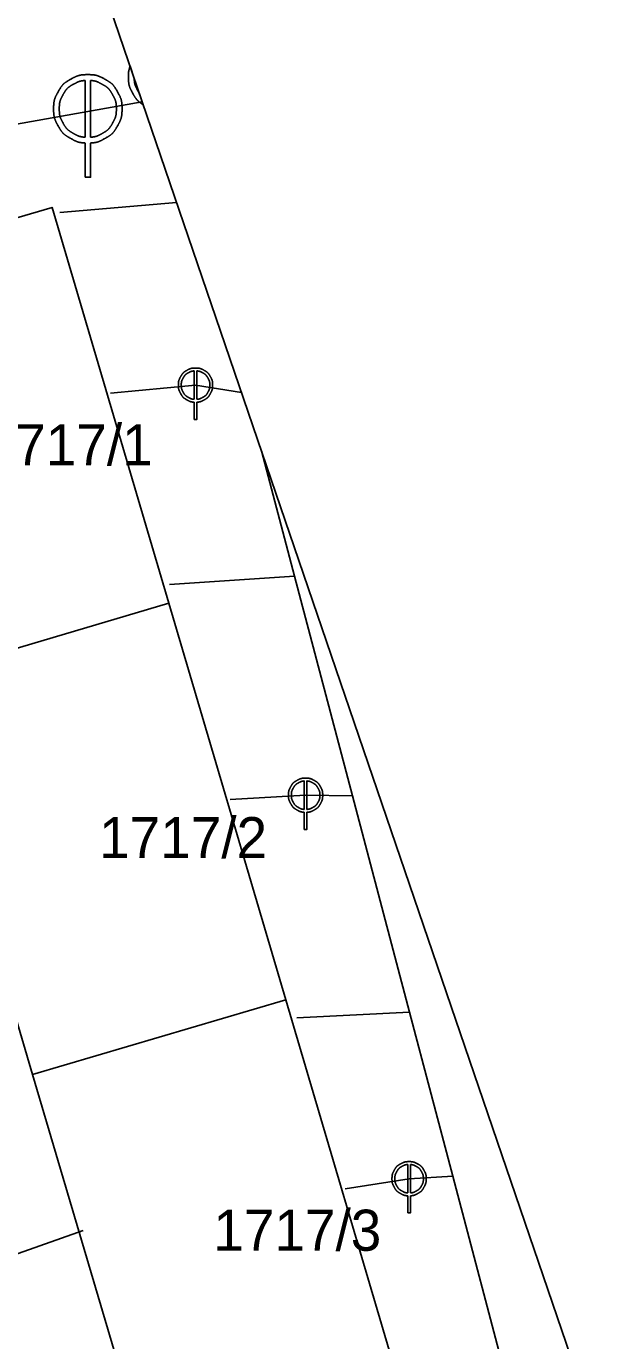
# Model space of a CAD drawing. Extents: x -562248 to -562040, y -1079385 to -1079027.
# Drawn here: x -562102.21 to -562081.38, y -1079149.79 to -1079101.77 of the extents above; entities that cross this region are included whole.
import ezdxf

# ---------------------------------------------------------------- set-up
doc = ezdxf.new("R2010")
doc.units = 0
for name, color, linetype in [('Default', 7, 'Continuous'), ('Kanalizační přípojka', 7, 'Continuous'), ('Kanalizační stoka', 7, 'Continuous'), ('Kanalizační šachta', 7, 'Continuous'), ('Parcela-polygon', 7, 'Continuous'), ('Parcela-text', 7, 'Continuous'), ('Vodovodní přípojka', 7, 'Continuous')]:
    doc.layers.add(name, color=color, linetype=linetype)

msp = doc.modelspace()

# ---------------------------------------------------------------- linework, layer by layer
at = {"layer": 'Default'}
for points in [[(-562099.963, -1079103.538), (-562100.174, -1079103.538), (-562100.38, -1079103.592), (-562100.578, -1079103.699)], [(-562099.349, -1079103.699), (-562099.548, -1079103.592), (-562099.753, -1079103.538), (-562099.963, -1079103.538)], [(-562100.578, -1079103.699), (-562100.777, -1079103.807), (-562100.932, -1079103.961), (-562101.044, -1079104.161)], [(-562100.866, -1079104.267), (-562100.773, -1079104.1), (-562100.644, -1079103.972), (-562100.478, -1079103.883)], [(-562100.478, -1079103.883), (-562100.335, -1079103.806), (-562100.197, -1079103.762), (-562100.065, -1079103.751)], [(-562099.86, -1079103.751), (-562099.728, -1079103.762), (-562099.592, -1079103.806), (-562099.45, -1079103.883)], [(-562099.45, -1079103.883), (-562099.284, -1079103.972), (-562099.154, -1079104.1), (-562099.061, -1079104.267)], [(-562098.881, -1079104.161), (-562098.994, -1079103.961), (-562099.149, -1079103.807), (-562099.349, -1079103.699)], [(-562101.044, -1079104.161), (-562101.157, -1079104.361), (-562101.213, -1079104.57), (-562101.213, -1079104.788)], [(-562101.005, -1079104.788), (-562101.005, -1079104.608), (-562100.959, -1079104.434), (-562100.866, -1079104.267)], [(-562099.061, -1079104.267), (-562098.967, -1079104.434), (-562098.92, -1079104.608), (-562098.92, -1079104.788)], [(-562098.713, -1079104.788), (-562098.713, -1079104.57), (-562098.769, -1079104.361), (-562098.881, -1079104.161)], [(-562101.213, -1079104.788), (-562101.213, -1079105.005), (-562101.158, -1079105.212), (-562101.048, -1079105.411)], [(-562100.869, -1079105.306), (-562100.96, -1079105.142), (-562101.005, -1079104.969), (-562101.005, -1079104.788)], [(-562098.92, -1079104.788), (-562098.92, -1079104.969), (-562098.966, -1079105.142), (-562099.057, -1079105.306)], [(-562098.878, -1079105.411), (-562098.768, -1079105.212), (-562098.713, -1079105.005), (-562098.713, -1079104.788)], [(-562101.048, -1079105.411), (-562100.938, -1079105.609), (-562100.784, -1079105.763), (-562100.585, -1079105.872)], [(-562100.483, -1079105.689), (-562100.649, -1079105.598), (-562100.777, -1079105.47), (-562100.869, -1079105.306)], [(-562099.057, -1079105.306), (-562099.148, -1079105.47), (-562099.276, -1079105.598), (-562099.44, -1079105.689)], [(-562099.34, -1079105.872), (-562099.142, -1079105.763), (-562098.988, -1079105.609), (-562098.878, -1079105.411)], [(-562100.585, -1079105.872), (-562100.411, -1079105.97), (-562100.238, -1079106.025), (-562100.065, -1079106.036)], [(-562100.065, -1079105.824), (-562100.202, -1079105.814), (-562100.341, -1079105.769), (-562100.483, -1079105.689)], [(-562099.44, -1079105.689), (-562099.584, -1079105.769), (-562099.724, -1079105.814), (-562099.86, -1079105.824)], [(-562099.86, -1079106.036), (-562099.688, -1079106.025), (-562099.514, -1079105.97), (-562099.34, -1079105.872)], [(-562096.571, -1079114.566), (-562096.627, -1079114.666), (-562096.655, -1079114.771), (-562096.655, -1079114.88)], [(-562096.338, -1079114.336), (-562096.437, -1079114.389), (-562096.515, -1079114.466), (-562096.571, -1079114.566)], [(-562096.55, -1079114.88), (-562096.55, -1079114.789), (-562096.527, -1079114.702), (-562096.48, -1079114.619)], [(-562096.48, -1079114.619), (-562096.434, -1079114.536), (-562096.369, -1079114.471), (-562096.286, -1079114.426)], [(-562096.03, -1079114.255), (-562096.136, -1079114.255), (-562096.238, -1079114.282), (-562096.338, -1079114.336)], [(-562096.286, -1079114.426), (-562096.215, -1079114.388), (-562096.146, -1079114.366), (-562096.081, -1079114.36)], [(-562095.722, -1079114.336), (-562095.822, -1079114.282), (-562095.924, -1079114.255), (-562096.03, -1079114.255)], [(-562095.979, -1079114.36), (-562095.912, -1079114.366), (-562095.844, -1079114.388), (-562095.774, -1079114.426)], [(-562095.774, -1079114.426), (-562095.691, -1079114.471), (-562095.626, -1079114.536), (-562095.578, -1079114.619)], [(-562095.489, -1079114.566), (-562095.545, -1079114.466), (-562095.623, -1079114.389), (-562095.722, -1079114.336)], [(-562095.578, -1079114.619), (-562095.531, -1079114.702), (-562095.508, -1079114.789), (-562095.508, -1079114.88)], [(-562095.405, -1079114.88), (-562095.405, -1079114.771), (-562095.433, -1079114.666), (-562095.489, -1079114.566)], [(-562096.655, -1079114.88), (-562096.655, -1079114.987), (-562096.627, -1079115.091), (-562096.572, -1079115.19)], [(-562096.482, -1079115.138), (-562096.527, -1079115.055), (-562096.55, -1079114.97), (-562096.55, -1079114.88)], [(-562095.508, -1079114.88), (-562095.508, -1079114.97), (-562095.53, -1079115.055), (-562095.576, -1079115.138)], [(-562095.487, -1079115.19), (-562095.432, -1079115.091), (-562095.405, -1079114.987), (-562095.405, -1079114.88)], [(-562096.572, -1079115.19), (-562096.517, -1079115.289), (-562096.439, -1079115.367), (-562096.34, -1079115.422)], [(-562096.289, -1079115.329), (-562096.372, -1079115.284), (-562096.436, -1079115.22), (-562096.482, -1079115.138)], [(-562096.34, -1079115.422), (-562096.254, -1079115.471), (-562096.168, -1079115.498), (-562096.081, -1079115.503)], [(-562096.081, -1079115.398), (-562096.15, -1079115.393), (-562096.219, -1079115.37), (-562096.289, -1079115.329)], [(-562095.769, -1079115.329), (-562095.84, -1079115.37), (-562095.91, -1079115.393), (-562095.979, -1079115.398)], [(-562095.979, -1079115.503), (-562095.892, -1079115.498), (-562095.805, -1079115.471), (-562095.717, -1079115.422)], [(-562095.576, -1079115.138), (-562095.621, -1079115.22), (-562095.686, -1079115.284), (-562095.769, -1079115.329)], [(-562095.717, -1079115.422), (-562095.618, -1079115.367), (-562095.541, -1079115.289), (-562095.487, -1079115.19)], [(-562092.318, -1079129.316), (-562092.417, -1079129.369), (-562092.495, -1079129.446), (-562092.551, -1079129.546)], [(-562092.46, -1079129.599), (-562092.414, -1079129.516), (-562092.349, -1079129.451), (-562092.266, -1079129.406)], [(-562092.01, -1079129.235), (-562092.116, -1079129.235), (-562092.218, -1079129.262), (-562092.318, -1079129.316)], [(-562092.266, -1079129.406), (-562092.195, -1079129.368), (-562092.126, -1079129.346), (-562092.061, -1079129.34)], [(-562091.702, -1079129.316), (-562091.802, -1079129.262), (-562091.904, -1079129.235), (-562092.01, -1079129.235)], [(-562091.959, -1079129.34), (-562091.892, -1079129.346), (-562091.824, -1079129.368), (-562091.754, -1079129.406)], [(-562091.754, -1079129.406), (-562091.671, -1079129.451), (-562091.606, -1079129.516), (-562091.558, -1079129.599)], [(-562091.469, -1079129.546), (-562091.525, -1079129.446), (-562091.603, -1079129.369), (-562091.702, -1079129.316)], [(-562092.551, -1079129.546), (-562092.607, -1079129.646), (-562092.635, -1079129.751), (-562092.635, -1079129.86)], [(-562092.635, -1079129.86), (-562092.635, -1079129.967), (-562092.607, -1079130.071), (-562092.552, -1079130.17)], [(-562092.53, -1079129.86), (-562092.53, -1079129.769), (-562092.507, -1079129.682), (-562092.46, -1079129.599)], [(-562092.462, -1079130.118), (-562092.507, -1079130.035), (-562092.53, -1079129.95), (-562092.53, -1079129.86)], [(-562091.558, -1079129.599), (-562091.511, -1079129.682), (-562091.488, -1079129.769), (-562091.488, -1079129.86)], [(-562091.488, -1079129.86), (-562091.488, -1079129.95), (-562091.51, -1079130.035), (-562091.556, -1079130.118)], [(-562091.385, -1079129.86), (-562091.385, -1079129.751), (-562091.413, -1079129.646), (-562091.469, -1079129.546)], [(-562091.467, -1079130.17), (-562091.412, -1079130.071), (-562091.385, -1079129.967), (-562091.385, -1079129.86)], [(-562092.552, -1079130.17), (-562092.497, -1079130.269), (-562092.419, -1079130.347), (-562092.32, -1079130.402)], [(-562092.269, -1079130.309), (-562092.352, -1079130.264), (-562092.416, -1079130.2), (-562092.462, -1079130.118)], [(-562092.32, -1079130.402), (-562092.234, -1079130.451), (-562092.148, -1079130.478), (-562092.061, -1079130.483)], [(-562092.061, -1079130.378), (-562092.13, -1079130.373), (-562092.199, -1079130.35), (-562092.269, -1079130.309)], [(-562091.749, -1079130.309), (-562091.82, -1079130.35), (-562091.89, -1079130.373), (-562091.959, -1079130.378)], [(-562091.959, -1079130.483), (-562091.872, -1079130.478), (-562091.785, -1079130.451), (-562091.697, -1079130.402)], [(-562091.556, -1079130.118), (-562091.601, -1079130.2), (-562091.666, -1079130.264), (-562091.749, -1079130.309)], [(-562091.697, -1079130.402), (-562091.598, -1079130.347), (-562091.521, -1079130.269), (-562091.467, -1079130.17)], [(-562088.538, -1079143.326), (-562088.637, -1079143.379), (-562088.715, -1079143.456), (-562088.771, -1079143.556)], [(-562088.68, -1079143.609), (-562088.634, -1079143.526), (-562088.569, -1079143.461), (-562088.486, -1079143.416)], [(-562088.23, -1079143.245), (-562088.336, -1079143.245), (-562088.438, -1079143.272), (-562088.538, -1079143.326)], [(-562088.486, -1079143.416), (-562088.415, -1079143.378), (-562088.346, -1079143.356), (-562088.281, -1079143.35)], [(-562087.922, -1079143.326), (-562088.022, -1079143.272), (-562088.124, -1079143.245), (-562088.23, -1079143.245)], [(-562088.179, -1079143.35), (-562088.112, -1079143.356), (-562088.044, -1079143.378), (-562087.974, -1079143.416)], [(-562087.974, -1079143.416), (-562087.891, -1079143.461), (-562087.826, -1079143.526), (-562087.778, -1079143.609)], [(-562087.689, -1079143.556), (-562087.745, -1079143.456), (-562087.823, -1079143.379), (-562087.922, -1079143.326)], [(-562088.771, -1079143.556), (-562088.827, -1079143.656), (-562088.855, -1079143.761), (-562088.855, -1079143.87)], [(-562088.855, -1079143.87), (-562088.855, -1079143.977), (-562088.827, -1079144.081), (-562088.772, -1079144.18)], [(-562088.75, -1079143.87), (-562088.75, -1079143.779), (-562088.727, -1079143.692), (-562088.68, -1079143.609)], [(-562088.682, -1079144.128), (-562088.727, -1079144.045), (-562088.75, -1079143.96), (-562088.75, -1079143.87)], [(-562087.778, -1079143.609), (-562087.731, -1079143.692), (-562087.708, -1079143.779), (-562087.708, -1079143.87)], [(-562087.708, -1079143.87), (-562087.708, -1079143.96), (-562087.73, -1079144.045), (-562087.776, -1079144.128)], [(-562087.605, -1079143.87), (-562087.605, -1079143.761), (-562087.633, -1079143.656), (-562087.689, -1079143.556)], [(-562087.687, -1079144.18), (-562087.632, -1079144.081), (-562087.605, -1079143.977), (-562087.605, -1079143.87)], [(-562088.772, -1079144.18), (-562088.717, -1079144.279), (-562088.639, -1079144.357), (-562088.54, -1079144.412)], [(-562088.489, -1079144.319), (-562088.572, -1079144.274), (-562088.636, -1079144.21), (-562088.682, -1079144.128)], [(-562088.281, -1079144.388), (-562088.35, -1079144.383), (-562088.419, -1079144.36), (-562088.489, -1079144.319)], [(-562087.969, -1079144.319), (-562088.04, -1079144.36), (-562088.11, -1079144.383), (-562088.179, -1079144.388)], [(-562087.776, -1079144.128), (-562087.821, -1079144.21), (-562087.886, -1079144.274), (-562087.969, -1079144.319)], [(-562087.917, -1079144.412), (-562087.818, -1079144.357), (-562087.741, -1079144.279), (-562087.687, -1079144.18)], [(-562088.54, -1079144.412), (-562088.454, -1079144.461), (-562088.368, -1079144.488), (-562088.281, -1079144.493)], [(-562088.179, -1079144.493), (-562088.092, -1079144.488), (-562088.005, -1079144.461), (-562087.917, -1079144.412)]]:
    msp.add_open_spline(points, degree=2, dxfattribs=at)
at = {"layer": 'Kanalizační přípojka'}
for points in [[(-562100.99, -1079108.57), (-562096.721, -1079108.213)], [(-562099.14, -1079115.18), (-562096.03, -1079114.88), (-562094.351, -1079115.153)], [(-562096.98, -1079122.16), (-562092.416, -1079121.861)], [(-562094.77, -1079130.02), (-562092.01, -1079129.86), (-562090.3, -1079129.88)], [(-562092.33, -1079137.99), (-562088.21, -1079137.78)], [(-562090.57, -1079144.24), (-562088.23, -1079143.87), (-562086.63, -1079143.78)]]:
    msp.add_lwpolyline(points, dxfattribs=at)
at = {"layer": 'Kanalizační stoka'}
msp.add_lwpolyline([(-562093.623, -1079117.284), (-562092.416, -1079121.861), (-562090.3, -1079129.88), (-562088.21, -1079137.78), (-562086.63, -1079143.78), (-562084.597, -1079151.5), (-562083.94, -1079153.99)], dxfattribs=at)
at = {"layer": 'Kanalizační šachta'}
for p, q in [((-562098.271, -1079103.674), (-562098.421, -1079103.233)), ((-562097.94, -1079104.641), (-562098.09, -1079104.202))]:
    msp.add_line(p, q, dxfattribs=at)
for points in [[(-562100.065, -1079103.751), (-562100.065, -1079105.824)], [(-562099.86, -1079105.824), (-562099.86, -1079103.751)], [(-562100.065, -1079107.288), (-562099.86, -1079107.288), (-562099.86, -1079106.036)], [(-562100.065, -1079106.036), (-562100.065, -1079107.288)], [(-562096.081, -1079114.36), (-562096.081, -1079115.398)], [(-562095.979, -1079115.398), (-562095.979, -1079114.36)], [(-562096.081, -1079116.13), (-562095.979, -1079116.13), (-562095.979, -1079115.503)], [(-562096.081, -1079115.503), (-562096.081, -1079116.13)], [(-562092.061, -1079129.34), (-562092.061, -1079130.378)], [(-562091.959, -1079130.378), (-562091.959, -1079129.34)], [(-562092.061, -1079131.11), (-562091.959, -1079131.11), (-562091.959, -1079130.483)], [(-562092.061, -1079130.483), (-562092.061, -1079131.11)], [(-562088.281, -1079143.35), (-562088.281, -1079144.388)], [(-562088.179, -1079144.388), (-562088.179, -1079143.35)], [(-562088.281, -1079145.12), (-562088.179, -1079145.12), (-562088.179, -1079144.493)], [(-562088.281, -1079144.493), (-562088.281, -1079145.12)]]:
    msp.add_lwpolyline(points, dxfattribs=at)
for points in [[(-562098.421, -1079103.233), (-562098.46, -1079103.355), (-562098.48, -1079103.481), (-562098.48, -1079103.61)], [(-562098.48, -1079103.61), (-562098.48, -1079103.826), (-562098.425, -1079104.034), (-562098.315, -1079104.233)], [(-562098.136, -1079104.128), (-562098.216, -1079103.983), (-562098.261, -1079103.832), (-562098.271, -1079103.674)], [(-562098.315, -1079104.233), (-562098.222, -1079104.401), (-562098.097, -1079104.537), (-562097.94, -1079104.641)], [(-562098.09, -1079104.202), (-562098.106, -1079104.178), (-562098.122, -1079104.153), (-562098.136, -1079104.128)]]:
    msp.add_open_spline(points, degree=2, dxfattribs=at)
at = {"layer": 'Parcela-polygon'}
msp.add_line((-562081.378, -1079153.144), (-562097.98, -1079104.526), dxfattribs=at)
for points in [[(-562089.427, -1079062.836), (-562106.84, -1079056.62), (-562119.65, -1079091.82), (-562121.03, -1079096.76), (-562122.05, -1079101.16), (-562122.69, -1079105.05), (-562122.92, -1079108.96), (-562097.98, -1079104.526)], [(-562097.98, -1079104.526), (-562101.498, -1079094.222), (-562089.427, -1079062.836)], [(-562097.98, -1079104.526), (-562122.92, -1079108.96), (-562122.79, -1079112.89), (-562122.55, -1079115.89), (-562121.94, -1079119.29), (-562120.22, -1079128.2), (-562118.94, -1079132.53), (-562115.47, -1079143.79), (-562113.13, -1079150.92), (-562110.57, -1079158.43), (-562109.03, -1079162.72), (-562081.378, -1079153.144)], [(-562101.27, -1079108.39), (-562097, -1079122.85), (-562092.73, -1079137.34), (-562088.46, -1079151.82), (-562097.7, -1079154.55), (-562101.98, -1079140.06), (-562106.25, -1079125.58), (-562110.52, -1079111.1), (-562101.27, -1079108.39)]]:
    msp.add_lwpolyline(points, dxfattribs=at)
for points in [[(-562110.52, -1079111.1), (-562101.27, -1079108.39), (-562097, -1079122.85), (-562106.25, -1079125.58)], [(-562097, -1079122.85), (-562092.73, -1079137.34), (-562101.98, -1079140.06), (-562106.25, -1079125.58)], [(-562092.73, -1079137.34), (-562088.46, -1079151.82), (-562097.7, -1079154.55), (-562101.98, -1079140.06)]]:
    msp.add_lwpolyline(points, close=True, dxfattribs=at)
at = {"layer": 'Vodovodní přípojka'}
msp.add_lwpolyline([(-562119.874, -1079152.505), (-562119.666, -1079152.467), (-562119.205, -1079152.27), (-562115.221, -1079151.096), (-562100.139, -1079145.758)], dxfattribs=at)

# ---------------------------------------------------------------- texts
at = {"layer": 'Parcela-text'}
for s, p in [('1717/1', (-562103.73, -1079117.81)), ('1717/2', (-562099.55, -1079132.16)), ('1717/3', (-562095.38, -1079146.5))]:
    msp.add_text(s, height=1.5, dxfattribs=at).set_placement(p)

doc.saveas('drawing.dxf')
